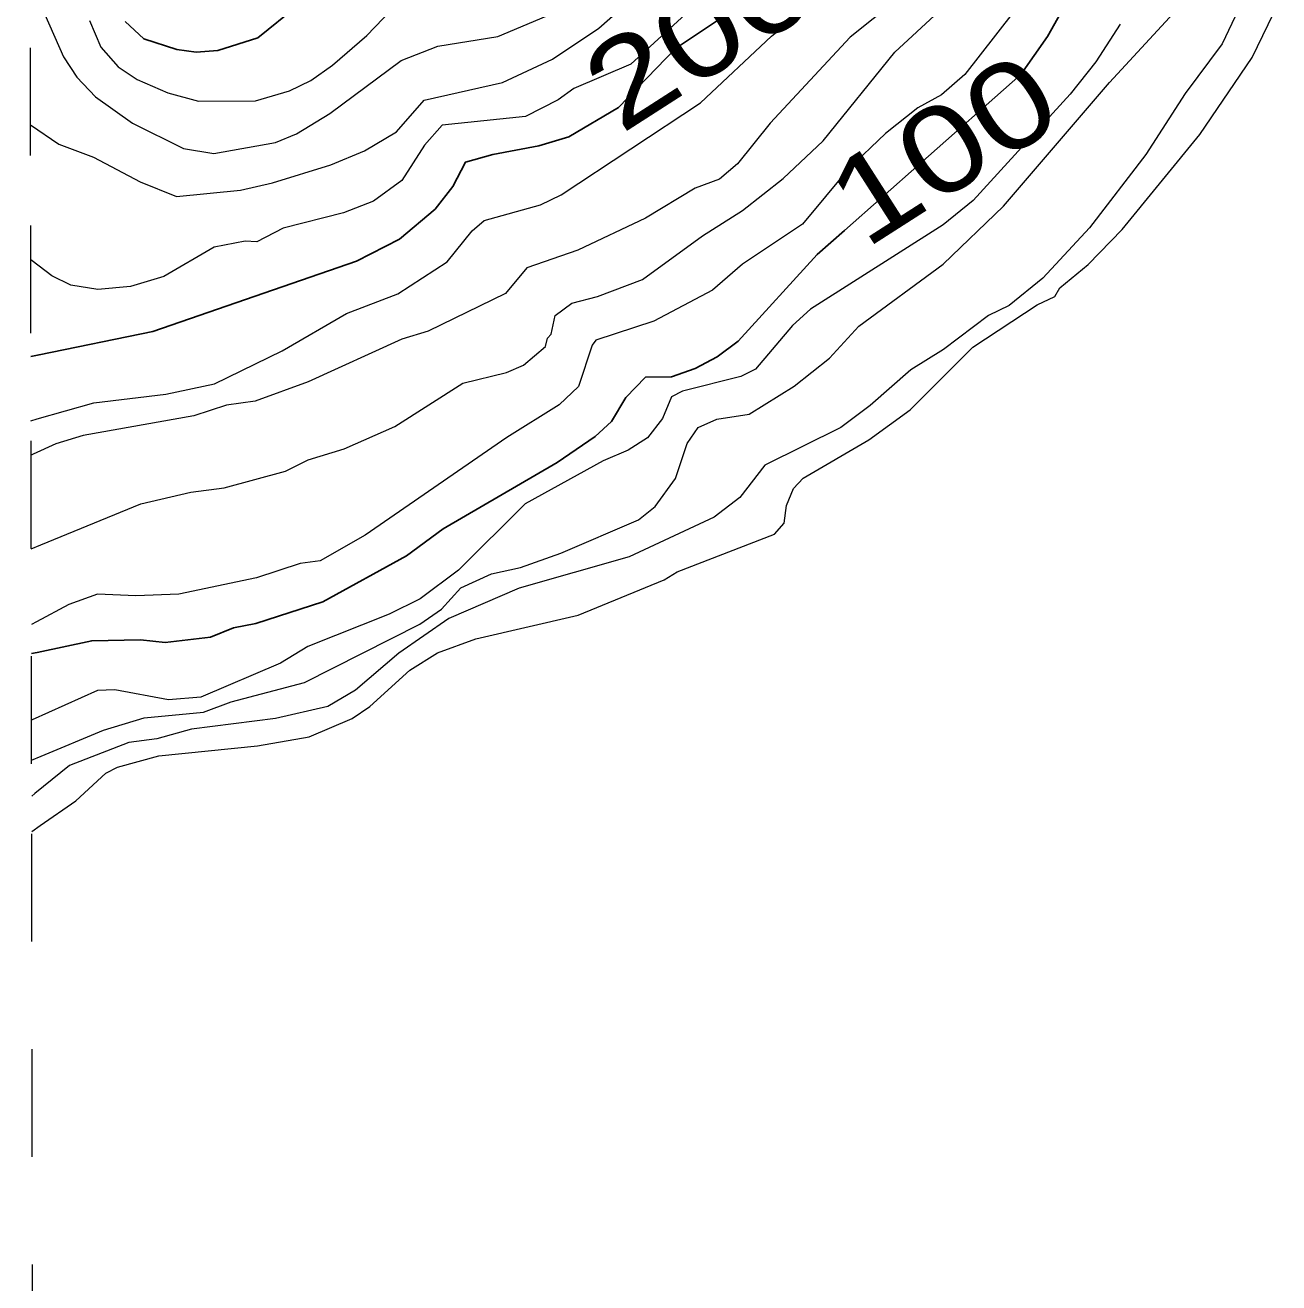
# Model space of a CAD drawing. Extents: x 474.5 to 500, y 7345.7 to 7373.4.
# Drawn here: x 474.558 to 475.722, y 7349.188 to 7350.356 of the extents above; entities that cross this region are included whole.
import ezdxf
from ezdxf.enums import TextEntityAlignment as Align

# ---------------------------------------------------------------- set-up
doc = ezdxf.new("R2010")
doc.units = 0
doc.header["$LTSCALE"] = 0.032
doc.linetypes.add('SHORT_DASHED', pattern=[2.7, 1.5, -1.2])
for name, color, linetype, lineweight in [('1', 7, 'Continuous', 25), ('2', 7, 'Continuous', 13), ('22', 7, 'SHORT_DASHED', 13)]:
    doc.layers.add(name, color=color, linetype=linetype, lineweight=lineweight)
doc.layers.add('61', color=7, linetype='Continuous')

msp = doc.modelspace()

# ---------------------------------------------------------------- linework, layer by layer
at = {"layer": '1'}
for points in [[(474.5639, 7349.7722), (474.5694, 7349.7734), (474.62, 7349.7842), (474.6653, 7349.785), (474.688, 7349.7827), (474.7301, 7349.7874), (474.7514, 7349.7963), (474.7722, 7349.8003), (474.8344, 7349.8203), (474.9121, 7349.8631), (474.9461, 7349.8881), (475.0521, 7349.9497), (475.0872, 7349.9737), (475.1023, 7349.9879), (475.1158, 7350.01), (475.1341, 7350.029), (475.158, 7350.0292), (475.18, 7350.037), (475.2006, 7350.0477), (475.22, 7350.0625), (475.2934, 7350.143), (475.3189, 7350.1652), (475.3886, 7350.2271), (475.4824, 7350.3101), (475.5073, 7350.3452), (475.5293, 7350.3847)], [(474.6509, 7350.3592), (474.6683, 7350.343), (474.6988, 7350.3331), (474.7169, 7350.3308), (474.7371, 7350.3324), (474.7741, 7350.3441), (474.8109, 7350.3737)], [(474.5634, 7350.0481), (474.5711, 7350.0497), (474.6765, 7350.0715), (474.8658, 7350.1367), (474.9056, 7350.1571), (474.9386, 7350.1848), (474.9553, 7350.206), (474.9668, 7350.2286), (474.9924, 7350.2358), (475.0351, 7350.2437), (475.0628, 7350.2521), (475.1091, 7350.2792), (475.1618, 7350.334), (475.2, 7350.3596)]]:
    msp.add_lwpolyline(points, dxfattribs=at)
at = {"layer": '2'}
for points in [[(475.4324, 7350.4312), (475.3241, 7350.3445), (475.2499, 7350.2647)], [(474.563, 7350.2632), (474.5895, 7350.2452), (474.6214, 7350.2332), (474.6648, 7350.2104), (474.6986, 7350.1967), (474.7579, 7350.2026), (474.7878, 7350.2094), (474.8419, 7350.2261), (474.873, 7350.2392), (474.9029, 7350.2567), (474.9285, 7350.2861), (475.0012, 7350.3025), (475.0477, 7350.3242), (475.0908, 7350.3529), (475.1618, 7350.4158)], [(474.5637, 7349.8696), (474.5726, 7349.8732), (474.6656, 7349.9113), (474.7119, 7349.9223), (474.7429, 7349.9262), (474.7999, 7349.9418), (474.8209, 7349.9523), (474.8542, 7349.9625), (474.9014, 7349.983), (474.9644, 7350.0233), (475.0051, 7350.0332), (475.0206, 7350.0402), (475.0411, 7350.0574), (475.043, 7350.0653), (475.0464, 7350.0688), (475.0502, 7350.0862), (475.0655, 7350.0977), (475.0894, 7350.1038), (475.1312, 7350.1196), (475.1869, 7350.1601), (475.224, 7350.1838), (475.2617, 7350.2134), (475.2991, 7350.2484), (475.3654, 7350.3307), (475.4636, 7350.4217)], [(475.6995, 7350.402), (475.6693, 7350.3385), (475.635, 7350.2922), (475.5986, 7350.2357), (475.5463, 7350.1677), (475.5028, 7350.121), (475.4715, 7350.0954), (475.4524, 7350.0863), (475.4108, 7350.0546), (475.3802, 7350.0357), (475.3427, 7350.0025), (475.3154, 7349.9822), (475.2447, 7349.9472), (475.2216, 7349.9172), (475.1977, 7349.899), (475.119, 7349.862), (475.0166, 7349.8331), (474.9513, 7349.8048), (474.9049, 7349.7728), (474.8649, 7349.7383), (474.8392, 7349.723), (474.7906, 7349.7121), (474.7124, 7349.7022), (474.6803, 7349.693), (474.6544, 7349.6898), (474.5994, 7349.6684), (474.567, 7349.6423), (474.5642, 7349.64)], [(474.5671, 7350.387), (474.5938, 7350.3265), (474.6061, 7350.3076), (474.6235, 7350.2893), (474.6579, 7350.2647), (474.7052, 7350.2413), (474.7334, 7350.2366), (474.7905, 7350.2468), (474.81, 7350.2548), (474.8409, 7350.2739), (474.9072, 7350.323), (474.9413, 7350.3364), (474.997, 7350.3454), (475.0477, 7350.3665)], [(475.4896, 7350.386), (475.4304, 7350.31), (475.4089, 7350.2912), (475.3867, 7350.2789), (475.3569, 7350.2551), (475.3225, 7350.2224), (475.2799, 7350.171), (475.2242, 7350.1338), (475.1961, 7350.1096), (475.1418, 7350.0809), (475.088, 7350.0634), (475.0844, 7350.0588), (475.0717, 7350.0204), (475.0539, 7350.0032), (475.0053, 7349.9729), (474.8738, 7349.8822), (474.832, 7349.8583), (474.8134, 7349.856), (474.7729, 7349.8426), (474.7007, 7349.8274), (474.6608, 7349.8258), (474.6252, 7349.8273), (474.5986, 7349.818)], [(474.6178, 7350.36), (474.6285, 7350.3355), (474.6444, 7350.317), (474.6621, 7350.3053), (474.6906, 7350.293), (474.719, 7350.2853), (474.772, 7350.2854), (474.8036, 7350.2947), (474.8232, 7350.3045), (474.8434, 7350.3186), (474.8752, 7350.3462), (474.9137, 7350.3863)], [(474.5635, 7349.9885), (474.5694, 7349.9902), (474.6219, 7350.0052), (474.6887, 7350.0132), (474.7339, 7350.0228), (474.7967, 7350.0535), (474.8565, 7350.0881), (474.9041, 7350.1064), (474.9498, 7350.136), (474.9731, 7350.1649), (474.9843, 7350.1743), (475.0364, 7350.1889), (475.0557, 7350.1981), (475.1851, 7350.2836), (475.2511, 7350.3456), (475.288, 7350.3754)], [(474.5641, 7349.6734), (474.573, 7349.6771), (474.6307, 7349.7012), (474.6685, 7349.7125), (474.7237, 7349.718), (474.7494, 7349.7276), (474.8175, 7349.7455), (474.9246, 7349.7996), (474.9445, 7349.8134), (474.9626, 7349.8334), (474.9911, 7349.8464), (475.0179, 7349.8521), (475.0554, 7349.8654), (475.1275, 7349.8966), (475.1429, 7349.9088), (475.162, 7349.935), (475.1726, 7349.9672), (475.183, 7349.9822), (475.2002, 7349.9898), (475.2302, 7349.9947), (475.2721, 7350.0205), (475.3048, 7350.0466), (475.3322, 7350.0764), (475.4103, 7350.1338), (475.4665, 7350.1877), (475.5649, 7350.3027), (475.6315, 7350.3749)], [(474.5642, 7349.6071), (474.5719, 7349.6125), (474.6051, 7349.6357), (474.6331, 7349.6613), (474.6439, 7349.6668), (474.6821, 7349.6773), (474.7738, 7349.6865), (474.8217, 7349.695), (474.8617, 7349.7119), (474.8782, 7349.723), (474.9153, 7349.757), (474.9408, 7349.7729), (474.9764, 7349.7859), (475.0716, 7349.8081), (475.1512, 7349.8407), (475.1633, 7349.8482), (475.2537, 7349.8831), (475.2627, 7349.8934), (475.265, 7349.9098), (475.2715, 7349.9256), (475.2803, 7349.9352), (475.3413, 7349.9708), (475.3797, 7349.9987), (475.438, 7350.0567), (475.4976, 7350.096), (475.5141, 7350.1038), (475.5186, 7350.1119), (475.545, 7350.1337), (475.5764, 7350.166), (475.6488, 7350.2544), (475.6972, 7350.3257), (475.722, 7350.3769)], [(475.1708, 7350.3657), (475.1205, 7350.3197), (475.0675, 7350.2971), (475.053, 7350.2865), (475.0226, 7350.2709), (474.9453, 7350.263), (474.9288, 7350.2445), (474.9079, 7350.2115), (474.8815, 7350.1925), (474.8536, 7350.1816), (474.7977, 7350.1672), (474.7732, 7350.1545), (474.7623, 7350.1552), (474.7336, 7350.1496), (474.6868, 7350.1223), (474.656, 7350.113), (474.6255, 7350.1105), (474.6005, 7350.1143), (474.5828, 7350.123), (474.5646, 7350.1369), (474.5633, 7350.1379)], [(475.5747, 7350.3567), (475.552, 7350.3217), (475.5284, 7350.2918), (475.4381, 7350.1929), (475.4105, 7350.1704), (475.2871, 7350.092), (475.2706, 7350.077), (475.2362, 7350.0364), (475.2225, 7350.0297), (475.1685, 7350.0159), (475.158, 7350.0106), (475.1499, 7349.9906), (475.1359, 7349.9727), (475.1179, 7349.9612), (475.0947, 7349.9512), (475.0224, 7349.9113), (474.9604, 7349.8498), (474.9249, 7349.8232), (474.8961, 7349.8088), (474.8204, 7349.7789), (474.7953, 7349.7633), (474.7211, 7349.7317), (474.6912, 7349.7293), (474.6414, 7349.7387), (474.6254, 7349.738), (474.5646, 7349.7109), (474.564, 7349.7106)], [(475.2499, 7350.2647), (475.2193, 7350.2269), (475.2027, 7350.2128), (475.18, 7350.2045), (475.1339, 7350.1766), (475.0711, 7350.1468), (475.0237, 7350.1306), (475.004, 7350.1067), (474.9323, 7350.0718), (474.9078, 7350.0643), (474.8207, 7350.0247), (474.7717, 7350.0068), (474.7451, 7350.0028), (474.7147, 7349.9929), (474.6121, 7349.9749), (474.5865, 7349.967), (474.5654, 7349.9574), (474.5636, 7349.9566)], [(474.5986, 7349.818), (474.5686, 7349.8019), (474.5639, 7349.7994)]]:
    msp.add_lwpolyline(points, dxfattribs=at)
at = {"layer": '22'}
msp.add_lwpolyline([(474.5711, 7345.7156), (474.5701, 7346.2805), (474.5691, 7346.8454), (474.5681, 7347.4103), (474.5671, 7347.9751), (474.5661, 7348.54), (474.5651, 7349.1049), (474.5641, 7349.6698), (474.5631, 7350.2347), (474.5621, 7350.7995), (474.5611, 7351.3644), (474.5601, 7351.9293), (474.5591, 7352.4942), (474.5581, 7353.059)], dxfattribs=at)

# ---------------------------------------------------------------- texts
at = {"layer": '61', "width": 1.25}
for s, rotation, p in [('200', 32.714, (475.2051, 7350.3143)), ('100', 32.619, (475.4317, 7350.2072))]:
    msp.add_text(s, height=0.08, rotation=rotation, dxfattribs=at).set_placement(p, align=Align.CENTER)

doc.saveas('drawing.dxf')
